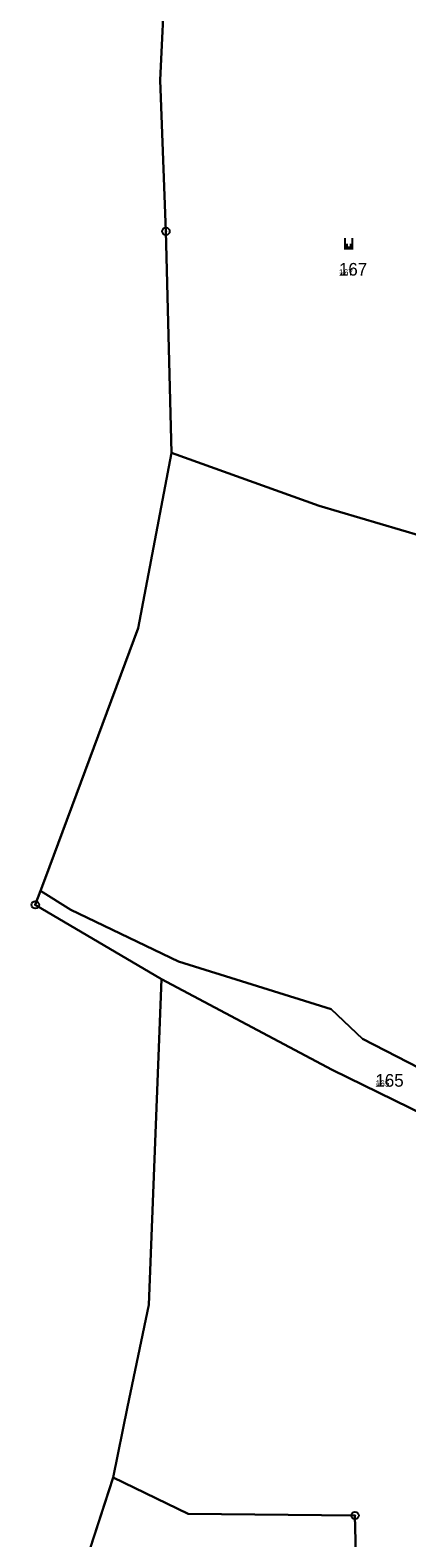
# Model space of a CAD drawing. Extents: x -759873 to -758487, y -975024 to -973516.
# Drawn here: x -759736.9 to -759686.2, y -974475 to -974272.1 of the extents above; entities that cross this region are included whole.
import ezdxf

# ---------------------------------------------------------------- set-up
doc = ezdxf.new("R2010")
doc.units = 0
for name, color, linetype in [('KAT_01_hranice KU', 7, 'Continuous'), ('KAT_02_hranice parcel', 7, 'Continuous'), ('KAT_03_1000_čísla parcelní', 7, 'Continuous'), ('KAT_03_250_čísla parcelní', 7, 'Continuous'), ('KAT_03_500_čísla parcelní', 7, 'Continuous'), ('KAT_05_1000_značky kultur', 7, 'Continuous'), ('KAT_05_250_značky kultur', 7, 'Continuous'), ('KAT_05_500_značky kultur', 7, 'Continuous'), ('KAT_11_značky bodu BP', 7, 'Continuous'), ('KAT_14_plocha_pozemek', 7, 'Continuous')]:
    doc.layers.add(name, color=color, linetype=linetype)

msp = doc.modelspace()

# ---------------------------------------------------------------- linework, layer by layer
at = {"layer": 'KAT_01_hranice KU'}
msp.add_lwpolyline([(-759718.73, -974264.72), (-759719.4, -974278.85), (-759718.64, -974299.18), (-759717.91, -974329), (-759722.36, -974352.57), (-759734.89, -974386.26), (-759735.51, -974387.92), (-759736.21, -974389.8), (-759719.23, -974399.82), (-759720.96, -974443.6), (-759723.79, -974457.34), (-759725.75, -974466.86), (-759731.24, -974483.81)], dxfattribs=at)
at = {"layer": 'KAT_02_hranice parcel'}
for p, q in [((-759717.91, -974329), (-759718.64, -974299.18)), ((-759722.36, -974352.57), (-759717.91, -974329)), ((-759734.89, -974386.26), (-759722.36, -974352.57)), ((-759735.51, -974387.92), (-759734.89, -974386.26)), ((-759736.21, -974389.8), (-759735.51, -974387.92)), ((-759719.23, -974399.82), (-759736.21, -974389.8)), ((-759720.96, -974443.6), (-759719.23, -974399.82)), ((-759731.24, -974483.81), (-759725.75, -974466.86))]:
    msp.add_line(p, q, dxfattribs=at)
for points in [[(-759718.64, -974299.18), (-759719.4, -974278.85), (-759718.73, -974264.72)], [(-759717.91, -974329), (-759698.03, -974336.1), (-759681.61, -974340.95), (-759677.07, -974340.17), (-759661.16, -974344.3), (-759650.27, -974349.95), (-759644.02, -974351.23)], [(-759719.23, -974399.82), (-759696.3, -974411.99), (-759654.6, -974432.4), (-759618.99, -974435.87), (-759618.64, -974431.31), (-759663, -974422.87), (-759692.19, -974407.83), (-759696.43, -974403.82), (-759716.94, -974397.44), (-759731.41, -974390.48), (-759735.51, -974387.92)], [(-759725.75, -974466.86), (-759723.79, -974457.34), (-759720.96, -974443.6)], [(-759692.66, -974493.88), (-759693.21, -974471.97), (-759715.67, -974471.76), (-759725.75, -974466.86)]]:
    msp.add_lwpolyline(points, dxfattribs=at)
at = {"layer": 'KAT_05_1000_značky kultur'}
for p, q in [((-759694.53, -974301.62), (-759694.53, -974300.12)), ((-759693.53, -974301.62), (-759693.53, -974300.12))]:
    msp.add_line(p, q, dxfattribs=at)
at = {"layer": 'KAT_05_250_značky kultur'}
for p, q in [((-759694.15, -974301.62), (-759694.15, -974301.24)), ((-759693.9, -974301.62), (-759693.9, -974301.24))]:
    msp.add_line(p, q, dxfattribs=at)
at = {"layer": 'KAT_05_500_značky kultur'}
for p, q in [((-759694.28, -974301.62), (-759694.28, -974300.87)), ((-759693.78, -974301.62), (-759693.78, -974300.87))]:
    msp.add_line(p, q, dxfattribs=at)
at = {"layer": 'KAT_11_značky bodu BP'}
for centre, radius in [((-759718.64, -974299.18), 0.5), ((-759718.64, -974299.18), 0.0303), ((-759736.21, -974389.8), 0.5), ((-759736.21, -974389.8), 0.0303), ((-759693.21, -974471.97), 0.5), ((-759693.21, -974471.97), 0.0303)]:
    msp.add_circle(centre, radius, dxfattribs=at)
at = {"layer": 'KAT_14_plocha_pozemek'}
for points in [[(-759661.16, -974344.3), (-759650.27, -974349.95), (-759644.02, -974351.23), (-759646.41, -974344.61), (-759674.19, -974267.79), (-759693.85, -974267.55), (-759700.24, -974246.4), (-759719.03, -974245.68), (-759718.73, -974264.72), (-759719.4, -974278.85), (-759718.64, -974299.18), (-759717.91, -974329), (-759698.03, -974336.1), (-759681.61, -974340.95), (-759677.07, -974340.17)], [(-759663, -974422.87), (-759692.19, -974407.83), (-759696.43, -974403.82), (-759716.94, -974397.44), (-759731.41, -974390.48), (-759735.51, -974387.92), (-759736.21, -974389.8), (-759719.23, -974399.82), (-759696.3, -974411.99), (-759654.6, -974432.4), (-759618.99, -974435.87), (-759618.64, -974431.31)], [(-759693.21, -974471.97), (-759715.67, -974471.76), (-759725.75, -974466.86), (-759731.24, -974483.81), (-759736.9, -974511.06), (-759707.2, -974511.06), (-759707.2, -974514.47), (-759690.36, -974516.4), (-759692.66, -974493.88)]]:
    msp.add_lwpolyline(points, close=True, dxfattribs=at)
for points in [[(-759681.61, -974340.95), (-759698.03, -974336.1), (-759717.91, -974329), (-759722.36, -974352.57), (-759734.89, -974386.26), (-759735.51, -974387.92), (-759731.41, -974390.48), (-759716.94, -974397.44), (-759696.43, -974403.82), (-759692.19, -974407.83), (-759663, -974422.87)], [(-759654.6, -974432.4), (-759696.3, -974411.99), (-759719.23, -974399.82), (-759720.96, -974443.6), (-759723.79, -974457.34), (-759725.75, -974466.86), (-759715.67, -974471.76), (-759693.21, -974471.97), (-759692.66, -974493.88)]]:
    msp.add_lwpolyline(points, dxfattribs=at)

# ---------------------------------------------------------------- texts
at = {"layer": 'KAT_03_1000_čísla parcelní'}
for s, p in [('167', (-759695.37, -974305.14)), ('165', (-759690.46, -974414.27))]:
    msp.add_text(s, height=1.7, dxfattribs=at).set_placement(p)
at = {"layer": 'KAT_03_250_čísla parcelní'}
for s, p in [('167', (-759695.37, -974305.14)), ('165', (-759690.46, -974414.27))]:
    msp.add_text(s, height=0.425, dxfattribs=at).set_placement(p)
at = {"layer": 'KAT_03_500_čísla parcelní'}
for s, p in [('167', (-759695.37, -974305.14)), ('165', (-759690.46, -974414.27))]:
    msp.add_text(s, height=0.85, dxfattribs=at).set_placement(p)

doc.saveas('drawing.dxf')
